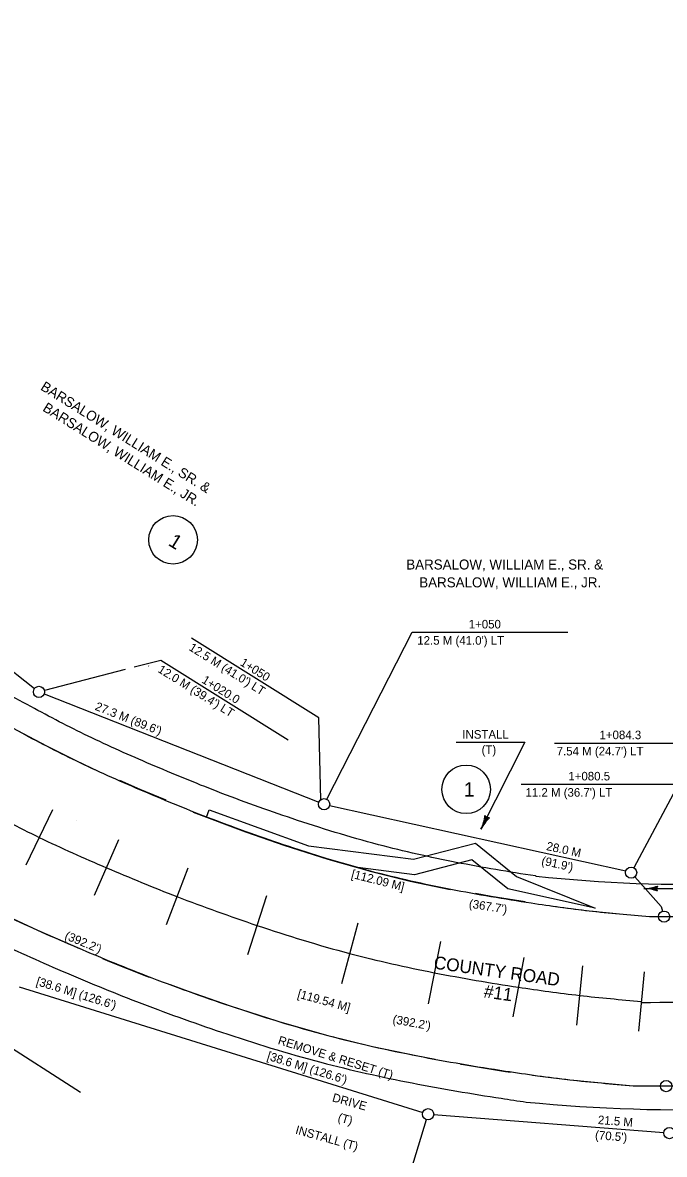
# Model space of a CAD drawing. Extents: x 435838 to 436160, y 121991 to 122158.
# Drawn here: x 435949.2 to 436006.3, y 122048.1 to 122148.7 of the extents above; entities that cross this region are included whole.
import ezdxf

# ---------------------------------------------------------------- set-up
doc = ezdxf.new("R2010")
doc.units = 0
for name, color, linetype in [('Level 1', 7, 'Continuous'), ('Level 12', 7, 'Continuous'), ('Level 16', 7, 'Continuous'), ('Level 2', 7, 'Continuous'), ('Level 3', 7, 'Continuous'), ('Level 4', 7, 'Continuous'), ('Level 5', 7, 'Continuous'), ('Level 6', 7, 'Continuous'), ('Level 7', 7, 'Continuous')]:
    doc.layers.add(name, color=color, linetype=linetype)

msp = doc.modelspace()

# ---------------------------------------------------------------- linework, layer by layer
at = {"layer": 'Level 1'}
for points in [[(435955.996, 122082.096), (435953.937, 122083.053), (435951.329, 122084.359), (435948.751, 122085.721), (435946.066, 122087.186), (435943.396, 122088.676), (435940.783, 122090.164), (435938.195, 122091.695), (435935.711, 122093.23), (435934.56, 122093.954)], [(435961.953, 122079.556), (435959.626, 122080.531), (435957.818, 122081.32)], [(435964.349, 122078.501), (435969.016, 122076.76), (435972.429, 122075.574), (435976.339, 122074.319), (435980.203, 122073.22), (435983.66, 122072.37), (435987.218, 122071.627), (435987.213, 122071.628)], [(435932.366, 122077.611), (435933.176, 122077.132), (435935.964, 122075.546), (435938.801, 122073.962), (435941.653, 122072.405), (435944.501, 122070.899), (435947.383, 122069.457), (435950.501, 122068.007), (435953.653, 122066.632), (435954.155, 122066.422)], [(435993.897, 122070.523), (435990.852, 122071.015), (435989.466, 122071.268)], [(436005.747, 122069.195), (436004.948, 122069.18), (436002.269, 122069.439), (435999.59, 122069.699), (435997.004, 122070.014), (435996.174, 122070.138)], [(435956.27, 122065.495), (435956.9, 122065.231), (435960.184, 122063.919), (435960.444, 122063.821)], [(435962.313, 122063.165), (435963.907, 122062.571), (435967.648, 122061.271), (435971.971, 122059.883), (435976.339, 122058.641), (435980.317, 122057.663), (435984.325, 122056.826), (435985.879, 122056.543)], [(435988.143, 122056.092), (435988.217, 122056.079), (435992.128, 122055.444), (435992.582, 122055.377)], [(435994.547, 122055.123), (435994.988, 122055.058), (435997.85, 122054.709), (436000.671, 122054.435), (436003.492, 122054.162), (436005.931, 122054.187)]]:
    msp.add_lwpolyline(points, dxfattribs=at)
for centre, radius, start, end in [((436008.511359, 122200.084174), 128, 263.87434448, 271.86219726), ((436008.286494, 122200.030697), 148, 264.45392496, 271.85649441)]:
    msp.add_arc(centre, radius, start, end, dxfattribs=at)
for points in [[(435994.853, 122072.818), (435994.799, 122072.826), (435987.758, 122074.037), (435980.829, 122075.611), (435973.165, 122077.931), (435966.495, 122080.333), (435960.581, 122082.753), (435955.004, 122085.266), (435949.907, 122087.888), (435944.606, 122090.814), (435939.461, 122093.8), (435934.548, 122096.864), (435929.717, 122099.937), (435924.69, 122103.244), (435919.749, 122106.472), (435914.495, 122109.875), (435907.307, 122114.552), (435900.62, 122118.921), (435895.314, 122122.449), (435890.117, 122125.878), (435884.475, 122129.419), (435879.049, 122132.772), (435873.963, 122135.625), (435869.112, 122138.27), (435864.391, 122140.737), (435859.418, 122142.994), (435854.572, 122145.114), (435849.023, 122147.125), (435844.3, 122148.715)], [(435837.918, 122129.761), (435842.425, 122128.243), (435847.15, 122126.532), (435851.276, 122124.726), (435855.619, 122122.755), (435859.692, 122120.626), (435864.283, 122118.123), (435868.895, 122115.536), (435873.901, 122112.443), (435879.293, 122109.058), (435884.27, 122105.775), (435889.612, 122102.223), (435896.383, 122097.798), (435903.605, 122093.101), (435908.843, 122089.706), (435913.726, 122086.518), (435918.851, 122083.145), (435923.888, 122079.94), (435929.149, 122076.66), (435934.754, 122073.408), (435940.497, 122070.238), (435946.316, 122067.244), (435952.683, 122064.375), (435959.317, 122061.661), (435966.875, 122058.939), (435975.711, 122056.265), (435983.844, 122054.417), (435991.761, 122053.054), (435993.982, 122052.72)]]:
    msp.add_spline(points, degree=3, dxfattribs=at)
at = {"layer": 'Level 12'}
for p, q in [((435951.845, 122078.717), (435949.475, 122073.793)), ((435953.981, 122077.763), (435953.974, 122077.747)), ((435957.72, 122076.045), (435955.544, 122071.082)), ((435963.866, 122073.52), (435961.946, 122068.473)), ((435970.868, 122071.065), (435969.172, 122065.805)), ((435978.989, 122068.631), (435977.551, 122063.245)), ((435986.354, 122067.003), (435985.247, 122061.451)), ((435993.768, 122065.591), (435992.792, 122060.289)), ((435998.975, 122064.836), (435998.465, 122059.572)), ((436004.475, 122064.303), (436003.965, 122059.039))]:
    msp.add_line(p, q, dxfattribs=at)
for points in [[(435841.109, 122139.238), (435845.724, 122137.684), (435850.861, 122135.823), (435855.347, 122133.86), (435860.005, 122131.746), (435864.402, 122129.448), (435869.123, 122126.874), (435873.972, 122124.154), (435879.188, 122120.931), (435884.705, 122117.468), (435889.792, 122114.112), (435895.116, 122110.572), (435901.845, 122106.175), (435909.05, 122101.488), (435914.296, 122098.089), (435919.208, 122094.881), (435924.284, 122091.541), (435929.218, 122088.402), (435934.305, 122085.23), (435939.68, 122082.111), (435945.202, 122079.063), (435950.66, 122076.255), (435956.632, 122073.564), (435962.906, 122070.997), (435970.02, 122068.435), (435978.27, 122065.938), (435985.801, 122064.227), (435993.28, 122062.94), (435998.72, 122062.204), (436004.22, 122061.671)], [(436004.196, 122061.568), (436017.518, 122061.982), (436030.094, 122063.223)]]:
    msp.add_spline(points, degree=3, dxfattribs=at)
at = {"layer": 'Level 16'}
for p, q in [((435990.305, 122078.207), (435990.467, 122078.018)), ((435990.341, 122078.061), (435990.327, 122077.851)), ((435990.576, 122077.943), (435990.415, 122077.807)), ((435990.715, 122078), (435990.466, 122078.019)), ((436005.55, 122071.835), (436005.356, 122071.753)), ((436005.55, 122071.572), (436005.356, 122071.654)), ((436005.664, 122071.933), (436005.569, 122071.703)), ((436005.664, 122071.474), (436005.569, 122071.704))]:
    msp.add_line(p, q, dxfattribs=at)
for centre, start, end in [((435993.007482, 122075.461349), 132.01753091, 153.24078369), ((435986.900367, 122078.542573), 333.21457262, 354.4378254), ((436004.429824, 122075.12369), 269.98689446, 291.21014723), ((436004.429824, 122068.28331), 68.78985277, 90.01310554)]:
    msp.add_arc(centre, 3.420733, start, end, dxfattribs=at)
at = {"layer": 'Level 2'}
for p, q in [((435954.334, 122053.582), (435862.989, 122111.831)), ((435938.049, 122099.106), (435950.239, 122089.504)), ((435951.097, 122089.012), (435975.534, 122079.393)), ((435976.487, 122079.103), (436002.847, 122073.299)), ((436003.649, 122072.746), (436005.987, 122070.113)), ((436005.987, 122070.113), (436006.107, 122069.688)), ((435948.86, 122062.957), (435984.769, 122051.79)), ((435985.744, 122051.603), (436006.215, 122050.002))]:
    msp.add_line(p, q, dxfattribs=at)
for points in [[(436004.948, 122069.18), (435999.59, 122069.699), (435994.426, 122070.398), (435987.277, 122071.628), (435980.201, 122073.235), (435972.392, 122075.599), (435965.614, 122078.04), (435959.611, 122080.496), (435953.937, 122083.053), (435948.751, 122085.721), (435943.396, 122088.676), (435938.195, 122091.695), (435933.239, 122094.785), (435928.382, 122097.875), (435923.344, 122101.19), (435918.41, 122104.413), (435913.158, 122107.815), (435905.965, 122112.494), (435899.268, 122116.871), (435893.958, 122120.401), (435888.788, 122123.812), (435883.176, 122127.335), (435877.802, 122130.655), (435872.774, 122133.476), (435867.955, 122136.103), (435863.313, 122138.529), (435858.418, 122140.751), (435853.661, 122142.832), (435848.213, 122144.806), (435843.516, 122146.387)], [(435838.702, 122132.089), (435843.235, 122130.562), (435848.061, 122128.814), (435852.276, 122126.969), (435856.697, 122124.963), (435860.849, 122122.793), (435865.472, 122120.272), (435870.142, 122117.653), (435875.2, 122114.527), (435880.622, 122111.124), (435885.626, 122107.823), (435890.964, 122104.273), (435897.725, 122099.856), (435904.942, 122095.161), (435910.182, 122091.765), (435915.072, 122088.572), (435920.186, 122085.207), (435925.197, 122082.019), (435930.415, 122078.765), (435935.964, 122075.546), (435941.653, 122072.405), (435947.383, 122069.457), (435953.653, 122066.632), (435960.198, 122063.954), (435967.648, 122061.271), (435976.339, 122058.641), (435984.325, 122056.826), (435992.134, 122055.482), (435997.85, 122054.709), (436003.492, 122054.162)], [(436029.353, 122070.73), (436017.03, 122069.514), (436004.948, 122069.18)], [(436003.492, 122054.162), (436018.006, 122054.45), (436030.835, 122055.716)]]:
    msp.add_spline(points, degree=3, dxfattribs=at)
at = {"layer": 'Level 3'}
for centre in [(435950.632, 122089.195), (435975.999, 122079.21), (436003.313858, 122073.122815), (436006.242384, 122069.212009), (436006.428628, 122054.141816), (435985.246, 122051.642), (436006.713, 122049.963)]:
    msp.add_circle(centre, 0.4997, dxfattribs=at)
at = {"layer": 'Level 5'}
for p, q in [((435976.227, 122079.655), (435983.824, 122094.501)), ((435983.824, 122094.501), (435997.676, 122094.501)), ((435975.538, 122086.898), (435964.201, 122093.982)), ((435961.473, 122091.996), (435959.103, 122091.384)), ((435960.384, 122091.505), (435960.41, 122091.489)), ((435972.81, 122084.912), (435961.473, 122091.996)), ((435958.306, 122091.178), (435951.116, 122089.32)), ((435975.695, 122079.607), (435975.538, 122086.898)), ((435996.502, 122084.642), (436009.873, 122084.642)), ((435993.538, 122080.982), (436007.53, 122080.982)), ((436007.53, 122080.982), (436003.557, 122073.553)), ((435982.807, 122043.675), (435985.1, 122051.164))]:
    msp.add_line(p, q, dxfattribs=at)
for centre in [(435962.562, 122102.721), (435988.634, 122080.529)]:
    msp.add_circle(centre, 2.16, dxfattribs=at)
at = {"layer": 'Level 6'}
for p, q in [((435965.551, 122078.063), (435965.777, 122078.695)), ((435965.777, 122078.695), (435974.614, 122075.515)), ((435974.614, 122075.515), (435983.94, 122074.312)), ((435983.94, 122074.312), (435989.455, 122075.747)), ((435989.455, 122075.747), (435993.125, 122072.79)), ((435989.135, 122074.259), (435984.026, 122072.929)), ((435992.343, 122071.674), (435989.135, 122074.259)), ((435984.026, 122072.929), (435978.995, 122073.578)), ((435993.125, 122072.79), (436000.111, 122069.951)), ((436000.111, 122069.951), (435992.343, 122071.674))]:
    msp.add_line(p, q, dxfattribs=at)
for points in [[(435978.996, 122073.578), (435976.276, 122074.352), (435972.392, 122075.599), (435968.989, 122076.782), (435965.551, 122078.063), (435965.551, 122078.065)], [(435978.996, 122073.578), (435976.276, 122074.352), (435972.392, 122075.599), (435968.989, 122076.782), (435965.614, 122078.04), (435965.551, 122078.065)]]:
    msp.add_lwpolyline(points, dxfattribs=at)
at = {"layer": 'Level 7'}
for p, q in [((435987.758, 122084.727), (435993.852, 122084.727)), ((435993.852, 122084.727), (435989.954, 122077.001)), ((436004.429, 122071.703), (436012.078, 122071.703))]:
    msp.add_line(p, q, dxfattribs=at)

# ---------------------------------------------------------------- texts
at = {"layer": 'Level 4'}
for s, p in [('BARSALOW, WILLIAM E., SR. &', (435950.703, 122116.113)), ('BARSALOW, WILLIAM E., JR.', (435950.893, 122114.238))]:
    msp.add_text(s, height=0.889002, rotation=327.99989998, dxfattribs=at).set_placement(p)
for s, p in [('BARSALOW, WILLIAM E., SR. &', (435983.308, 122100.082)), ('BARSALOW, WILLIAM E., JR.', (435984.462, 122098.493))]:
    msp.add_text(s, height=0.889002, dxfattribs=at).set_placement(p)
at = {"layer": 'Level 5'}
for s, height, rotation, p in [('1', 1.270002, 327.99989998, (435962.056, 122102.288)), ("12.5 M (41.0') LT", 0.761874, 327.99989998, (435963.904, 122092.954)), ("12.0 M (39.4') LT", 0.761874, 327.99989998, (435961.142, 122091.006)), ('1+050', 0.761874, 327.99989998, (435968.459, 122091.612)), ('1+020.0', 0.761874, 327.99989998, (435965.051, 122090.068)), ('COUNTY ROAD', 1.142712, 351.99989995, (435985.702, 122064.593)), ('#11', 1.142712, 351.99989995, (435990.152, 122062.032))]:
    msp.add_text(s, height=height, rotation=rotation, dxfattribs=at).set_placement(p)
for s, height, p in [('1+050', 0.761874, (435988.862, 122094.841)), ("12.5 M (41.0') LT", 0.761874, (435984.287, 122093.394)), ('1+084.3', 0.761874, (436000.5, 122084.993)), ("7.54 M (24.7') LT", 0.761874, (435996.687, 122083.546)), ('1+080.5', 0.761874, (435997.727, 122081.325)), ('1', 1.270002, (435988.435, 122079.894)), ("11.2 M (36.7') LT", 0.761874, (435993.914, 122079.878))]:
    msp.add_text(s, height=height, dxfattribs=at).set_placement(p)
at = {"layer": 'Level 7'}
for s, height, rotation, p in [("27.3 M (89.6')", 0.761874, 338.51418955, (435955.558, 122087.622)), ('28.0 M', 0.761868, 347.58206018, (435995.721, 122075.143)), ("(91.9')", 0.761868, 347.58206018, (435995.285, 122073.845)), ('[112.09 M]', 0.761874, 345.76998187, (435978.362, 122072.669)), ("(367.7')", 0.761874, 350.99593048, (435988.842, 122070.017)), ("(392.2')", 0.761868, 337.5265447, (435952.856, 122067.244)), ("[38.6 M] (126.6')", 0.761874, 342.72447184, (435950.324, 122063.143)), ('[119.54 M]', 0.761874, 344.46864174, (435973.572, 122062.024)), ("(392.2')", 0.761874, 349.68890577, (435982.051, 122059.735)), ('REMOVE & RESET (T)', 0.761874, 342.72360778, (435971.837, 122057.899)), ("[38.6 M] (126.6')", 0.761862, 342.72447184, (435970.862, 122056.508)), ('DRIVE', 0.761874, 344.45731138, (435976.667, 122052.793)), ('(T)', 0.761874, 344.45731138, (435977.163, 122051.033)), ('21.5 M', 0.761868, 355.52810307, (436000.333, 122050.774)), ('INSTALL (T)', 0.761874, 344.45731138, (435973.391, 122049.923)), ("(70.5')", 0.761868, 355.52810307, (436000.081, 122049.428))]:
    msp.add_text(s, height=height, rotation=rotation, dxfattribs=at).set_placement(p)
for s, p in [('INSTALL', (435988.296, 122085.04)), ('(T)', (435990.009, 122083.678))]:
    msp.add_text(s, height=0.761874, dxfattribs=at).set_placement(p)

doc.saveas('drawing.dxf')
